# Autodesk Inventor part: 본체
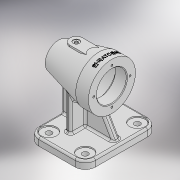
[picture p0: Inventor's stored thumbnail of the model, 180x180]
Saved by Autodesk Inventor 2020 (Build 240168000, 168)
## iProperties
Created: 2024-12
Part Number: 본체
Material: 일반
Document SubType Name: Modeling
Designer: 1강의실14
Density: 1 g/cm^3
Appearance: 기본값
Author: 1강의실14
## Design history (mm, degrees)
sketch "스케치1"
  geometry: L1 (-42, 37)-(42, 37); L2 (42, 37)-(42, 0); L3 (42, 0)-(-42, 0); L4 (-42, 0)-(-42, 37); L5 (-42, 21)-(22, 37); L6 (22, 37)-(42, 37); L7 (-42, 21)-(-42, 0); L8 (42, 37)-(42, 0); 1 further point
  constraints: 16 end point, 3 equal length, 2 perpendicular, 2 point on line, 1 horizontal, 1 midpoint, 1 vertical
  dimensions: "d0" = 84 distance of L3.end L2.end; "d2" = 42 distance from line of point (0, 0) L4; "d3" = 20 distance of L1.end L5.end; "d5" = 74 diameter of L1 L3; "d6" = 42 diameter of L5.start L3
revolve "회전1" sketch "스케치1" stored, may be unused: angle "d7" = 90 deg
sketch "스케치2"
  geometry: L1 (-42, 21)-(22, 37) reference; L2 (22, 37)-(42, 37) reference; L3 (-42, -21)-(-42, 21) reference; L4 (-42, 0)-(42, 0); L5 (-34, 0)-(-34, 15.5); L6 (-34, 15.5)-(-31, 15.5); L7 (-31, 15.5)-(-31, 17.5); L8 (-31, 17.5)-(-21, 17.5); L9 (-21, 17.5)-(-21, 21.096); L10 (24, 32.346)-(24, 23.5); L11 (24, 23.5)-(42, 23.5); L12 (24, 32.346)-(-21, 21.096); L13 (42, -37)-(42, 37) reference; L14 (42, 23.5)-(42, 0); 1 further point
  constraints: 20 end point, 5 perpendicular, 2 midpoint, 2 point on line, 1 collinear, 1 horizontal, 1 parallel, 1 vertical
  dimensions: "d11" = 5 distance between parallel lines of L1 L12; "d14" = 3 distance of L5.end L6.end; "d17" = 45 horizontal distance of L10.start L9.end; "d18" = 18 distance of L10.end L11.end; "d19" = 47 diameter of L11 L4; "d20" = 10 distance of L7.end L8.end; "d21" = 35 diameter of L8 L4; "d22" = 31 diameter of L6 L4
revolve "회전2" sketch "스케치2" stored, may be unused: angle "d23" = 90 deg
node "작업 평면1"
sketch "스케치3"
  geometry: L1 (32, -57)-(-57, -57); L2 (-57, -57)-(-57, 57); L3 (-57, 57)-(32, 57); L4 (32, 57)-(32, -57); L5 (-42, 37)-(-42, -37) reference; 1 further point
  constraints: 8 end point, 2 parallel, 1 horizontal, 1 perpendicular
  dimensions: "d25" = 89 distance of L2.end L3.end; "d26" = 114 distance of L1.end L2.end; "d27" = 15 distance between parallel lines of L2 L5; "d28" = 57 distance from line of point (0, 0) L1
extrude "돌출1" join sketch "스케치3" distance "d29" = 12; taper "d30" = 0 deg
sketch "스케치5"
  geometry: L1 (-3, -28)-(5, -28); L2 (5, -28)-(5, 28); L3 (5, 28)-(-3, 28); L4 (-3, 28)-(-3, -28); L5 (-32, 57)-(-32, -57) reference; 1 further point
  constraints: 8 end point, 2 parallel, 1 horizontal, 1 perpendicular
  dimensions: "d33" = 28 distance from line of point (0, 0) L1; "d34" = 56 distance of L1.end L2.end; "d36" = 8 distance between parallel lines of L2 L4; "d53" = 29 distance between parallel lines of L4 L5
extrude "돌출2" join sketch "스케치5" stored distance "d37" = 12; taper "d38" = 0 deg
sketch "스케치6"
  geometry: L1 (-42, -21)-(22, -37) reference; L2 (-32, -82)-(-32, -70) reference; L3 (57, -70)-(-32, -70) reference; L4 (-32, -23.5)-(-32, -70); L5 (30.947, -37)-(50, -70); L6 (57, -82)-(57, -70) reference; L7 (22, -37)-(42, -37) reference; 1 further point
  constraints: 4 end point, 3 point on line, 1 vertical
  dimensions: "d39" = 7 distance from line of L6 L5.end; "d40" = 60 deg angle of L3 L5
feature "리브1" dims "d41" = 1, "d42" = 10, "d43" = 0, "d44" = 0, "d45" = 1, "d46" = 1
feature "리브2" dims "d47" = 1, "d48" = 10, "d49" = 0, "d50" = 0, "d51" = 1, "d52" = 1
sketch "스케치7"
  geometry: L1 (-32, 57)-(-32, -57) reference; C1 r 12 at (-16, -41); 2 further points
  constraints: 1 centre point, 1 coincident
  dimensions: "d54" = 16 distance from line of point (-16, -41) L1; "d55" = 41 vertical distance of point (0, 0) point (-16, -41); "d56" = 24 diameter of C1
extrude "돌출3" cut sketch "스케치7" distance "d57" = 2; taper "d58" = 0 deg
sketch "스케치8"
  geometry: 1 further point
sketch "스케치9"
  geometry: C1 r 12 at (0, 0) reference; 2 further points
  constraints: 1 coincident
hole "구멍1" sketch "스케치9" at (0, 0) diameter "d59" = 9; stored, may be unused: countersink angle "d63" = 90 deg, drill point angle "d65" = 118 deg; dims "d60" = 6, "d61" = 4, "d62" = 2, "d64" = 8
sketch "스케치10" dims "d72" = 57
  geometry: 3 further points
  constraints: 2 vertical alignment, 1 coincident, 2 other
hole "구멍2" sketch "스케치10" at (0, 28.5) diameter "d73" = 3.242; stored, may be unused: countersink angle "d77" = 90 deg, drill point angle "d79" = 120 deg; dims "d74" = 8, "d75" = 4, "d76" = 2, "d78" = 10
node "작업 평면2"
sketch "스케치11"
  geometry: L1 (-42, 37)-(-42, -37) reference; L2 (14, -10)-(-11.736, -10); L3 (-5, -5)-(-5, -28) reference; L4 (14, 10)-(-11.736, 10); L5 (-22, 37)-(-22, -37) reference; L6 (-24, -23.5)-(-24, 23.5) reference; L7 (42, 21)-(42, -21) reference; L8 (32, 5)-(3, 5) reference; L9 (3, 5)-(3, 28) reference; L10 (3, 28)-(-5, 28) reference; L11 (-5, 28)-(-5, 5) reference; L12 (-5, 5)-(-22, 5) reference; L13 (-22, -5)-(-22, 5) reference; L14 (-22, -5)-(-5, -5) reference; L15 (-5, -5)-(-5, -28) reference; L16 (-5, -28)-(3, -28) reference; L17 (3, -28)-(3, -5) reference; L18 (3, -5)-(32, -5) reference; L19 (32, -5)-(32, 5) reference; L20 (-11.736, 10)-(-11.736, -10); A1 r 10 centre (14, 0) between (14, -10) and (14, 10); 3 further points
  constraints: 6 end point, 2 point on circle, 1 centre point, 1 horizontal, 1 perpendicular, 1 vertical
  dimensions: "d84" = 20 diameter of A1; "d85" = 56 distance from line of L1 A1.centre; "d88" = 10 distance from line of point (0, 0) L2; "d89" = 10 distance from line of L4 point (0, 0); "d96" = 19 distance from line of L2.start L3; "d115" = 11.7358 distance from line of L20 point (0, 0)
extrude "돌출4" join sketch "스케치11" distance "d97" = 2.783; taper "d98" = 0 deg
sketch "스케치13"
  geometry: C1 r 5 at (-14, 0); A1 r 10 centre (-14, 0) between (-14, 10) and (-14, -10) reference; 1 further point
  constraints: 1 centre point, 1 coincident
  dimensions: "d101" = 10 diameter of C1
extrude "돌출5" cut sketch "스케치13" distance "d102" = 1; taper "d103" = 0 deg
sketch "스케치14"
  geometry: C1 r 5 at (0, 0) reference; 2 further points
  constraints: 1 coincident
hole "구멍3" sketch "스케치14" at (0, 0) diameter "d104" = 5.1881; stored, may be unused: countersink angle "d108" = 90 deg, drill point angle "d110" = 120 deg; dims "d105" = 14.5, "d106" = 4, "d107" = 2, "d109" = 16
node "작업 평면3"
fillet "모깎기1" dims "d116" = 5
fillet "모깎기2" dims "d117" = 0.3
fillet "모깎기3" dims "d118" = 3
chamfer "모따기1" distance "d119" = 1; stored, may be unused: second distance "d120" = 2, angle "d121" = 45 deg
fillet "모깎기4" dims "d122" = 3
chamfer "모따기2" distance "d123" = 1; stored, may be unused: second distance "d124" = 2, angle "d125" = 45 deg
sketch "스케치15"
  geometry: L1 (-10, 37)-(-10, -37) reference; 2 further points
  constraints: 1 horizontal alignment, 1 other
  dimensions: "d111" = 9 distance from line of L1 point (-1, 0)
feature "엠보싱1" sketch "스케치15" dims "d0" = 84, "d2" = 42, "d3" = 20, "d5" = 74, "d6" = 42, "d112" = 0.5, "d113" = 0
fillet "모깎기5" dims "d126" = 3
fillet "모깎기6" dims "d127" = 3
fillet "모깎기7" dims "d128" = 16
fillet "모깎기8" dims "d129" = 3
node "솔리드1"
pattern_linear "직사각형 패턴1" dims "d68" = 82, "d71" = 57
pattern_circular "원형 패턴1" dims angle "d81" = 360 deg
node "투영된 루프3"
feature "A9D066F2-1C7D-4E18-AEED-F7BC21143FA4" dims "d59" = 9, "d60" = 6, "d61" = 4, "d62" = 2, "d63" = 90 deg, "d64" = 8, "d65" = 118 deg
other parameters: "d24" = -82, "d83" = -115
